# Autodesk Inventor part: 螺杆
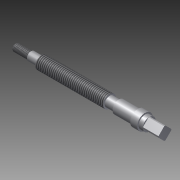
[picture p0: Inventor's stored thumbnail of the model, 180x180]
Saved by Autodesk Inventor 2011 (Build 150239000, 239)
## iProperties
Created: 2013-11
Part Number: 螺杆
Document SubType Name: Modeling
Designer: user
Density: 1 g/cm^3
Author: user
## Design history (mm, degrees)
sketch "草图1"
  geometry: L1 (0, 0)-(0, 5); L2 (0, 5)-(22, 5); L3 (22, 5)-(22, 6); L4 (22, 6)-(37, 6); L5 (37, 6)-(37, 9); L6 (37, 9)-(133, 9); L7 (133, 9)-(133, 7); L8 (133, 7)-(146, 7); L9 (146, 7)-(146, 9); L10 (146, 9)-(173, 9); L11 (173, 9)-(173, 11); L12 (173, 11)-(183, 11); L13 (183, 11)-(183, 9); L14 (183, 9)-(211, 9); L15 (211, 9)-(211, 0); L16 (211, 0)-(0, 0)
  constraints: 32 end point, 6 perpendicular, 5 parallel, 4 point on line, 1 vertical
  dimensions: "d0" = 5 distance of L1.start L1.end; "d1" = 22 distance of L1.end L2.end; "d2" = 1 distance of L2.end L3.end; "d3" = 15 distance of L3.end L4.end; "d4" = 3 distance of L4.end L5.end; "d5" = 96 distance of L5.end L6.end; "d6" = 2 distance of L6.end L7.end; "d7" = 13 distance of L7.end L8.end; "d8" = 2 distance of L8.end L9.end; "d9" = 27 distance of L9.end L10.end; "d10" = 2 distance of L10.end L11.end; "d11" = 10 distance of L11.end L12.end; "d12" = 2 distance of L12.end L13.end (derived); "d13" = 28 distance of L13.end L14.end
revolve "旋转1" sketch "草图1" stored, may be unused: angle "d14" = 90 deg
sketch "草图2"
  geometry: L1 (0.95, -8.95)-(8.95, -0.95); L2 (8.95, 0.95)-(0.95, 8.95); L3 (-0.95, 8.95)-(-8.95, 0.95); L4 (-8.95, -0.95)-(-0.95, -8.95); 4 further points
  constraints: 8 end point, 2 parallel, 2 vertical alignment, 1 horizontal alignment, 1 perpendicular, 9 other
  dimensions: "d15" = 14 distance of point (-9.899, 0) point (0, -9.899); "d16" = 14 distance of point (0, 9.899) point (-9.899, 0)
extrude "拉伸1" cut sketch "草图2" distance "d17" = 22; taper "d18" = 0 deg
feature "螺纹1" dims "d19" = 10, "d20" = 0
feature "螺纹2" dims "d21" = 10, "d22" = 0
chamfer "倒角1" distance "d23" = 1; stored, may be unused: second distance "d24" = 2, angle "d25" = 45 deg
node "实体1"
